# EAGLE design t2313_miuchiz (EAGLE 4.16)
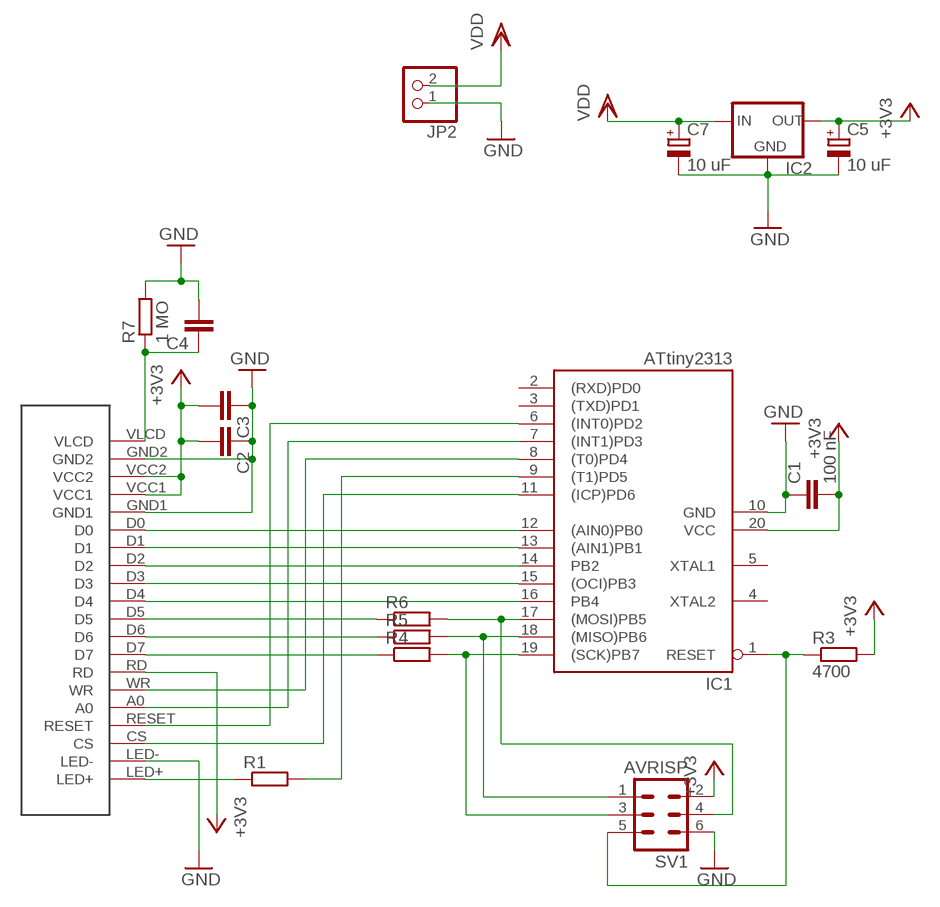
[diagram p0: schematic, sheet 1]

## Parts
C1  100 nF  C-EUC1206  [C1206]
C2  C-EUC0805  [C0805]
C3  C-EUC0805  [C0805]
C4  C-EUC0805  [C0805]
C5  10 uF  CPOL-EU153CLV-0405  [153CLV-0405]
C7  10 uF  CPOL-EU153CLV-0405  [153CLV-0405]
IC1  ATtiny2313  AT90S2313S  [SO20L]
IC2  AD73XXP  [SOT89R]
JP2  PINHD-1X2  [1X02]
LCD2  DISPLAY_WOOLWORTH1  [DISPLAYWOOL2]
R1  R-EU_M0805  [M0805]
R3  4700  R-EU_M0805  [M0805]
R4  R-EU_M0805  [M0805]
R5  R-EU_M0805  [M0805]
R6  R-EU_M0805  [M0805]
R7  1 MO  R-EU_M0805  [M0805]
SV1  AVRISP  MA03-2  [MA03-2]

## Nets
+3V3: C1.2 C2.2 C3.2 C5.+ IC1.20(VCC) IC2.1(OUT) LCD2.RD LCD2.VCC1 LCD2.VCC2 R3.2 SV1.2
GND: C1.1 C2.1 C3.1 C4.2 C5.- C7.- IC1.10(GND) IC2.2(GND) JP2.1 LCD2.GND1 LCD2.GND2 LCD2.LED- R7.2 SV1.6
N$1: IC1.12((AIN0)PB0) LCD2.D0
N$2: IC1.13((AIN1)PB1) LCD2.D1
N$3: IC1.14(PB2) LCD2.D2
N$4: IC1.15((OCI)PB3) LCD2.D3
N$5: IC1.16(PB4) LCD2.D4
N$6: IC1.11((ICP)PD6) LCD2.CS
N$7: IC1.18((MISO)PB6) R5.2 SV1.1
N$8: IC1.17((MOSI)PB5) R6.2 SV1.4
N$9: LCD2.LED+ R1.1
N$13: IC1.8((T0)PD4) LCD2.WR
N$14: LCD2.D5 R6.1
N$15: IC1.1(RESET) R3.1 SV1.5
N$16: IC1.19((SCK)PB7) R4.2 SV1.3
N$17: LCD2.D6 R5.1
N$18: LCD2.D7 R4.1
N$19: IC1.9((T1)PD5) R1.2
N$20: C4.1 LCD2.VLCD R7.1
N$21: IC1.6((INT0)PD2) LCD2.RESET
N$23: IC1.7((INT1)PD3) LCD2.A0
VDD: C7.+ IC2.3(IN) JP2.2
Unconnected: IC1.2((RXD)PD0) IC1.3((TXD)PD1) IC1.4(XTAL2) IC1.5(XTAL1)

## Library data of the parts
C1-C4 = rcl:C-EU: CAPACITOR, European symbol
C5 C7 = rcl:CPOL-EU: POLARIZED CAPACITOR, European symbol
IC1 = atmel:AT90S2313: MICROCONTROLLER 2 Kbytes FLASH 128 bytes SRAM 128 bytes EEPROM UART
IC2 = ad73xx:AD73XX: Positiv Voltage Regulators www.torex.co.jp/english/product/pro02/pdf/0201_xc62fp.pdf
JP2 = pinhead:PINHD-1X2: PIN HEADER
LCD2 = Display_woolworthv2:DISPLAY_WOOLWORTH1
R1 R3-R7 = rcl:R-EU_: RESISTOR, European symbol
SV1 = con-lstb:MA03-2: PIN HEADER

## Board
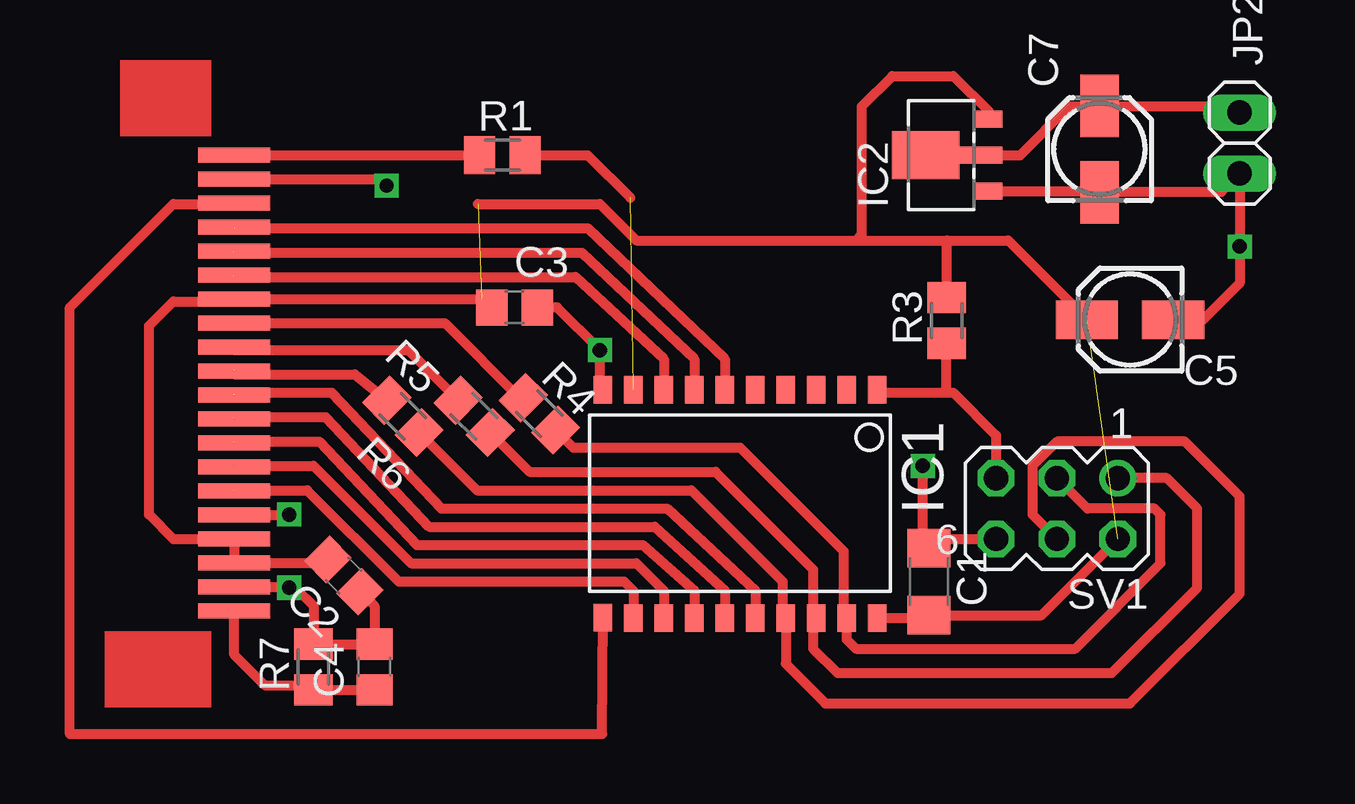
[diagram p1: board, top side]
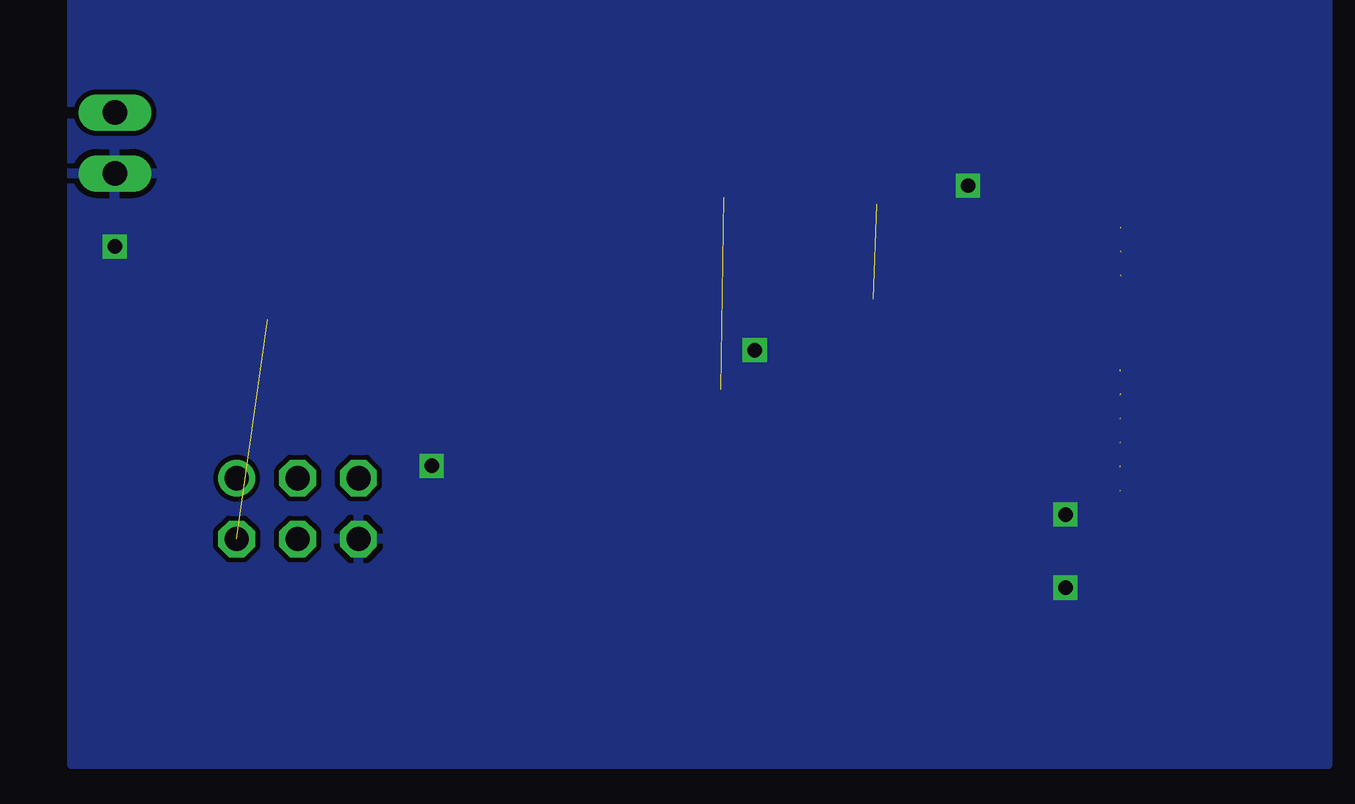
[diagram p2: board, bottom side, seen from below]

No outline drawn. Coordinates in mm, seen from the top.
Copper layers (1*16): Top 0.035mm / dielectric 1.5mm / Bottom 0.035mm
Design rules "default": minimum track width 10mil, minimum drill 24mil, track to track 8mil, track to pad 8mil, pad to pad 8mil, via to via 8mil, smd to smd 8mil, copper to edge 40mil, drill to drill 8mil, minimum pad ring 10mil, minimum via ring 8mil, stop-mask expansion 4mil, vias tented up to drill 0mil, thermal gap 10mil

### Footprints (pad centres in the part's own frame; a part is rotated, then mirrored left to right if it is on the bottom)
C1206 = smd 1.6 x 1.8: 1 -1.4,0; 2 1.4,0
C0805 = smd 1.3 x 1.5: 1 -0.95,0; 2 0.95,0
153CLV-0405 = smd 2.6 x 1.6: + 1.8,0; - -1.8,0
SO20L = smd 0.762 x 1.143: 1 -5.08,-5.131; 2 -3.81,-5.131; 3 -2.54,-5.131; 4 -1.27,-5.131; 5 0,-5.131; 6 1.27,-5.131; 7 2.54,-5.131; 8 3.81,-5.131; 9 5.08,-5.131; 10 6.35,-5.131; 11 6.35,4.369; 12 5.08,4.394; 13 3.81,4.394; 14 2.54,4.394; 15 1.27,4.394; 16 0,4.394; 17 -1.27,4.394; 18 -2.54,4.394; 19 -3.81,4.394; 20 -5.08,4.394
SOT89R = smd 0.7 x 1.1: 1 1.5,-1.75; 2 -1.5,-1.75 | smd 0.7 x 1.8: 3 0,-1.4 | smd 2 x 2.8: 4 0,0.9
1X02 = drill 1.016 long: 1 -1.27,0; 2 1.27,0
DISPLAYWOOL2 = smd 3 x 0.635: A0 0,-4; CS 0,-2; D0 0,-14; D1 0,-13; D2 0,-12; D3 0,-11; D4 0,-10; D5 0,-9; D6 0,-8; D7 0,-7; GND1 0,-15; GND2 0,-18; LED+ 0,0; LED- 0,-1; RD 0,-6; RESET 0,-3; VCC1 0,-16; VCC2 0,-17; VLCD 0,-19; WR 0,-5
M0805 = smd 1.3 x 1.6: 1 -0.95,0; 2 0.95,0
MA03-2 = drill 1.016 round: 1 -2.54,-1.27 | drill 1.016 octagon: 2 -2.54,1.27; 3 0,-1.27; 4 0,1.27; 5 2.54,-1.27; 6 2.54,1.27

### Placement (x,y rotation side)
C1  75.18,24.89 270 top
C2  50.8,25.15 135 top
C3  57.91,36.32 180 top
C4  52.07,21.34 90 top
C5  83.57,35.81 180 top
C7  82.3,42.93 90 top
IC1  67.94,27.77 180 top
IC2  75.95,42.67 90 top
JP2  88.14,43.18 90 top
LCD2  46.23,42.67 0 top
R1  57.4,42.67 0 top
R3  75.91,35.78 90 top
R4  58.94,31.89 315 top
R5  56.23,31.78 315 top
R6  53.26,31.78 315 top
R7  49.53,21.34 90 top
SV1  80.52,27.94 180 top

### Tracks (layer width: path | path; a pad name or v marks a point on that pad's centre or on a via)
+3V3  (2 unrouted)
  Top 0.406: IC2.1 77.7,44.48 76.2,45.97 73.66,45.97 72.39,44.7 72.39,39.37 72.14,39.12 | C5.+ 81.79,35.81 78.49,39.12 75.95,39.12 | 72.14,39.12 75.95,39.12 | R3.2 75.91,39.08 75.95,39.12 | LCD2.VCC2 46.23,25.65 | LCD2.VCC2 LCD2.VCC1 43.69,26.67 42.67,27.69 42.67,35.56 43.69,36.58 46.23,36.58 LCD2.RD 56.55,36.67 56.9,36.32 C3.2 | IC1.20 75.18,23.37 C1.2 79.88,23.49 SV1.2 | 72.14,39.12 62.99,39.12 61.47,40.64 56.39,40.64 | C2.2 50.04,25.91 49.8,25.67 LCD2.VCC2 | C2.2
GND  (via drill 0.6)
  Top 0.406: 82.3,41.15 87.38,41.15 JP2.1 v88.14,38.86 88.14,37.34 86.61,35.81 C5.- | 82.3,41.15 C7.- | IC2.2 82.27,41.17 82.3,41.15 | C1.1 75.18,26.16 | SV1.6 75.69,26.67 75.18,26.16 | IC1.10 61.59,33.02 61.47,33.02 v61.47,34.54 59.69,36.32 C3.1 | v74.93,29.72 74.93,26.42 75.18,26.16 | LCD2.LED- 52.31,41.67 v52.58,41.4 | LCD2.GND1 48.5,27.67 v48.51,27.69 | LCD2.GND2 48.48,24.67 v48.51,24.64 48.77,24.64 49.53,23.88 R7.2 52,22.29 arc90 52.07,22.35 | 52.07,22.35 C4.2 | C2.1 52.07,23.88 52.07,22.35
  pour Bottom: 37.59,50.04 37.59,17.27 89.92,17.27 89.92,50.04
N$1  (1 unrouted)
  Top 0.406: IC1.12 62.86,24.51 62.48,24.89 53.09,24.89 49.28,28.7 46.23,28.7
N$2  (1 unrouted)
  Top 0.406: IC1.13 64.13,24.51 62.99,25.65 53.59,25.65 49.53,29.72 46.23,29.72 46.21,29.7
N$3  (1 unrouted)
  Top 0.406: IC1.14 65.4,24.51 63.25,26.42 53.85,26.42 49.78,30.73 46.23,30.73 46.2,30.7
N$4  (1 unrouted)
  Top 0.406: IC1.15 66.67,24.51 63.75,27.18 54.36,27.18 50.04,31.75 46.23,31.75 46.2,31.72
N$5  (1 unrouted)
  Top 0.406: IC1.16 67.94,24.51 64.26,27.94 54.86,27.94 50.29,32.77 46.23,32.77 46.2,32.73
N$6
  Top 0.406: IC1.11 61.56,18.54 39.37,18.54 39.37,36.32 43.69,40.64 46.23,40.64 LCD2.CS
N$7
  Top 0.406: 70.36,23.37 70.36,22.1 71.37,21.08 82.8,21.08 86.36,24.64 86.36,27.94 85.09,29.21 SV1.1 | R5.2 58.54,29.46 66.29,29.46 70.36,25.4 70.36,23.37 | 70.36,23.37 IC1.18
N$8
  Top 0.406: R6.2 56.34,28.7 65.28,28.7 69.09,24.89 69.09,23.37 IC1.17 69.21,21.46 70.87,19.81 83.57,19.81 88.14,24.38 88.14,28.45 85.85,30.73 80.52,30.73 79.5,29.72 79.5,27.69 SV1.4
N$9
  Top 0.406: LCD2.LED+ R1.1
N$13  (1 unrouted)
  Top 0.406: IC1.8 64.13,34.16 60.45,37.59 46.23,37.59 46.2,37.62
N$14  (1 unrouted)
  Top 0.406: 46.23,33.74 46.23,33.53 51.26,33.53 R6.1
N$15
  Top 0.406: SV1.5 77.98,30.99 76.2,32.77 75.95,32.77 | IC1.1 73.15,32.77 75.95,32.77 | R3.1 75.91,32.8 75.95,32.77
N$16
  Top 0.406: R4.2 60.35,30.48 67.31,30.48 71.63,26.16 71.63,23.37 IC1.19 71.75,22.48 72.14,22.1 81.28,22.1 84.84,25.65 84.84,27.69 84.58,27.94 81.79,27.94 SV1.3
N$17
  Top 0.406: LCD2.D6 46.23,34.54 53.46,34.54 R5.1
N$18
  Top 0.406: R4.1 58.21,32.56 58.17,32.51 55.01,35.67 LCD2.D7
N$19  (1 unrouted)
  Top 0.406: R1.2 60.96,42.67 62.74,40.89
N$20
  Top 0.406: LCD2.VLCD 46.23,21.84 47.5,20.57 49.53,20.57 R7.1 52,20.39 arc-90 52.07,20.32 C4.1
N$21  (1 unrouted)
  Top 0.406: IC1.6 66.67,34.16 60.96,39.62 46.23,39.62 46.2,39.66
N$23  (1 unrouted)
  Top 0.406: IC1.7 65.4,34.16 60.71,38.61 46.23,38.61 46.2,38.64
VDD
  Top 0.406: JP2.2 88.14,44.7 82.55,44.7 C7.+ 82.06,44.73 82.04,44.7 81.03,44.7 78.99,42.67 IC2.3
